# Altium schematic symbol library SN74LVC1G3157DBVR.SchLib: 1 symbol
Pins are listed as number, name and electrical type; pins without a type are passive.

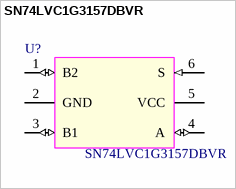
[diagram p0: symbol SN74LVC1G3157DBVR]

## SN74LVC1G3157DBVR
designator U?
IC, SWITCH, SPDT, SOT23-6; Manufacturer: TEXAS INSTRUMENTS; SymbolCreator: x0199378
pins: 1 B2 (io), 2 GND (power), 3 B1 (io), 4 A (io), 5 VCC (power), 6 S (in)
